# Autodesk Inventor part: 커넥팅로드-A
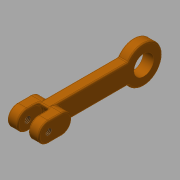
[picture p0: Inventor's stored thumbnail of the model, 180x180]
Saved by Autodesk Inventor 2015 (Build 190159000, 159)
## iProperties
Created: 2018-01
Part Number: 커넥팅로드-A
Material: 알루미늄 6061
Document SubType Name: Modeling
Designer: mduedu
Density: 2.71 g/cm^3
Appearance: 주황색
Mass: 5.11804 g
Surface Area: 16.3537 cm^2
Volume: 1.88857 cm^3
Author: mduedu
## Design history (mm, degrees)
sketch "스케치1"
  geometry: L1 (0, 0)-(0, 40); L2 (3.75, 40)-(3.75, 5.911); L3 (-3.75, 40)-(-3.75, 5.911); A1 r 7 centre (0, 0) between (3.75, 5.911) and (-3.75, 5.911); A2 r 3.75 centre (0, 40) between (3.75, 40) and (-3.75, 40); 1 further point
  constraints: 6 end point, 4 point on circle, 2 centre point, 2 coincident, 2 parallel, 2 tangent, 1 vertical
  dimensions: "d1" = 40 distance of L1.start L1.end; "d2" = 7.5 diameter of A2; "d3" = 14 diameter of A1
extrude "돌출1" new body sketch "스케치1" stored distance "d4" = 4; taper "d5" = 0 deg
sketch "스케치2"
  geometry: L1 (-3.75, 40)-(-3.75, 35); L2 (3.75, 40)-(3.75, 35); A1 r 3.75 centre (0, 40) between (3.75, 40) and (-3.75, 40) reference; A2 r 3.75 centre (0, 40) between (3.75, 40) and (-3.75, 40); A3 r 3.75 centre (0, 35) between (-3.75, 35) and (3.75, 35); 1 further point
  constraints: 4 end point, 4 point on circle, 2 centre point, 2 tangent, 1 coincident, 1 equal radius, 1 point on line, 1 vertical alignment
  dimensions: "d6" = 5 distance of A3.centre A1.centre
extrude "돌출2" join sketch "스케치2" stored distance "d7" = 12; taper "d8" = 0 deg
sketch "스케치3"
  geometry: L1 (3.75, 40)-(3.75, 38); L2 (-3.75, 40)-(-3.75, 38); A1 r 3.75 centre (0, 40) between (3.75, 40) and (-3.75, 40) reference; A2 r 3.75 centre (0, 40) between (3.75, 40) and (-3.75, 40); A3 r 3.75 centre (0, 38) between (-3.75, 38) and (3.75, 38); 1 further point
  constraints: 4 end point, 4 point on circle, 3 tangent, 2 centre point, 1 coincident, 1 equal radius, 1 parallel, 1 point on line
  dimensions: "d9" = 2 distance of A3.centre A1.centre
extrude "돌출3" cut sketch "스케치3" stored distance "d10" = 4; taper "d11" = 0 deg
fillet "모깎기5" dims "d16" = 0.5
fillet "모깎기6" dims "d17" = 0.5
fillet "모깎기7" dims "d18" = 0.5
fillet "모깎기8" dims "d19" = 0.5
hole "구멍1" diameter "d22" = 7.5; stored, may be unused: countersink angle "d26" = 90 deg, drill point angle "d28" = 118 deg; dims "d20" = 10, "d21" = 10, "d23" = 6, "d24" = 4, "d25" = 2, "d27" = 8
sketch "스케치4"
  geometry: A1 r 3.75 centre (40, 0) between (40, -3.75) and (40, 3.75) reference; 2 further points
  constraints: 1 coincident
sketch "스케치5"
  geometry: 1 further point
  constraints: 1 other
hole "구멍2" sketch "스케치5" at (40, 0) diameter "d29" = 2.459; stored, may be unused: countersink angle "d33" = 90 deg, drill point angle "d35" = 0 deg; dims "d30" = 6, "d31" = 4, "d32" = 2, "d34" = 8
sketch "스케치6"
  geometry: 1 further point
  constraints: 1 other
hole "구멍4" sketch "스케치6" at (-40, 0) diameter "d36" = 2.459; stored, may be unused: countersink angle "d40" = 90 deg, drill point angle "d42" = 0 deg; dims "d37" = 6, "d38" = 4, "d39" = 2, "d41" = 8
node "솔리드1"
